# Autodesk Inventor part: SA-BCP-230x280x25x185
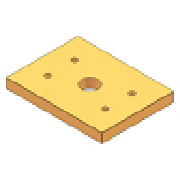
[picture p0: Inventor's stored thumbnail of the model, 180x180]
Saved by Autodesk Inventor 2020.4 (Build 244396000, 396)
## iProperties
Created: 2019-01
Part Number: SA-BCP-230x280x25x185
Material: S 55 C
Description: Bottom Clamping Plate
Document SubType Name: Modeling
Designer: mel
Standard Revision: 1
Manufacturer: FUTABA
Language: fr-FR
Size Designation: 230x280x25x185
Categories: <MemberInstance><Categories><Category DisplayName="Moule" InternalName="349578f2-f4d4-4954-8c09-8e99297a61c0" Mnemonic="MOLD"><Category DisplayName="Plaque de m
Density: 7.85 g/cm^3
Appearance: Orange (Pale)
IsCustomPart: 1
Author: mel
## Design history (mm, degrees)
sketch "Sketch1"
  geometry: L1 (-140, 115)-(140, 115); L2 (140, 115)-(140, -115); L3 (140, -115)-(-140, -115); L4 (-140, -115)-(-140, 115); C1 r 17.5 at (0, 0); 4 further points
  constraints: 8 end point, 2 midpoint, 2 parallel, 1 centre point, 1 coincident, 1 horizontal, 1 horizontal alignment, 1 perpendicular, 1 vertical alignment
  dimensions: "d72" = 280 distance between parallel lines of L2 L4 (= W_); "d73" = 230 distance between parallel lines of L3 L1 (= L); "d74" = 35 diameter of C1 (= dB); "d75" = 92.5 horizontal distance of point (0, 0) point (-92.5, 53) (= 0.5 x S1_W); "d76" = 53 vertical distance of point (0, 0) point (-92.5, 53) (= 0.5 x S1_L)
hole "Hole1" sketch "Sketch1" diameter "d79" = 14 (= S1_d1); stored, may be unused: countersink angle "d83" = 90 deg, drill point angle "d85" = 0 deg; dims "d80" = 6, "d81" = 20 (= S1_d2), "d82" = 13 (= S1_k), "d84" = 25 (= H_)
pattern_linear "Rectangular Pattern1" dims "d88" = 106 (computed from S1_L, Ns), "d91" = 185 (computed from S1_W, Nw)
chamfer "Chamfer1" distance "d94" = 0.5; stored, may be unused: second distance "d95" = 2, angle "d96" = 45 deg
body "Solid1"
extrude "Extrusion1" new body sketch "Sketch1" distance "d77" = 25 (= H_); taper "d78" = 0 deg
extrude "Extrusion2" cut sketch "Sketch1" distance "d92" = 25 (= H_); taper "d93" = 0 deg
other parameters: "L" = 230 [user parameter; used in 1 equation term], "W_" = 280 [user parameter; used in 1 equation term], "H_" = 25 [user parameter; used in 3 equation terms], "S1_W" = 185 [user parameter; used in 2 equation terms], "S1_d1" = 14 [user parameter; used in 1 equation term], "S1_d2" = 20 [user parameter; used in 1 equation term], "S1_k" = 13 [user parameter; used in 1 equation term], "S1_L" = 106 [user parameter; used in 2 equation terms], "dB" = 35 [user parameter; used in 1 equation term]
